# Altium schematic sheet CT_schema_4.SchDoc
size 309 x 315 mm
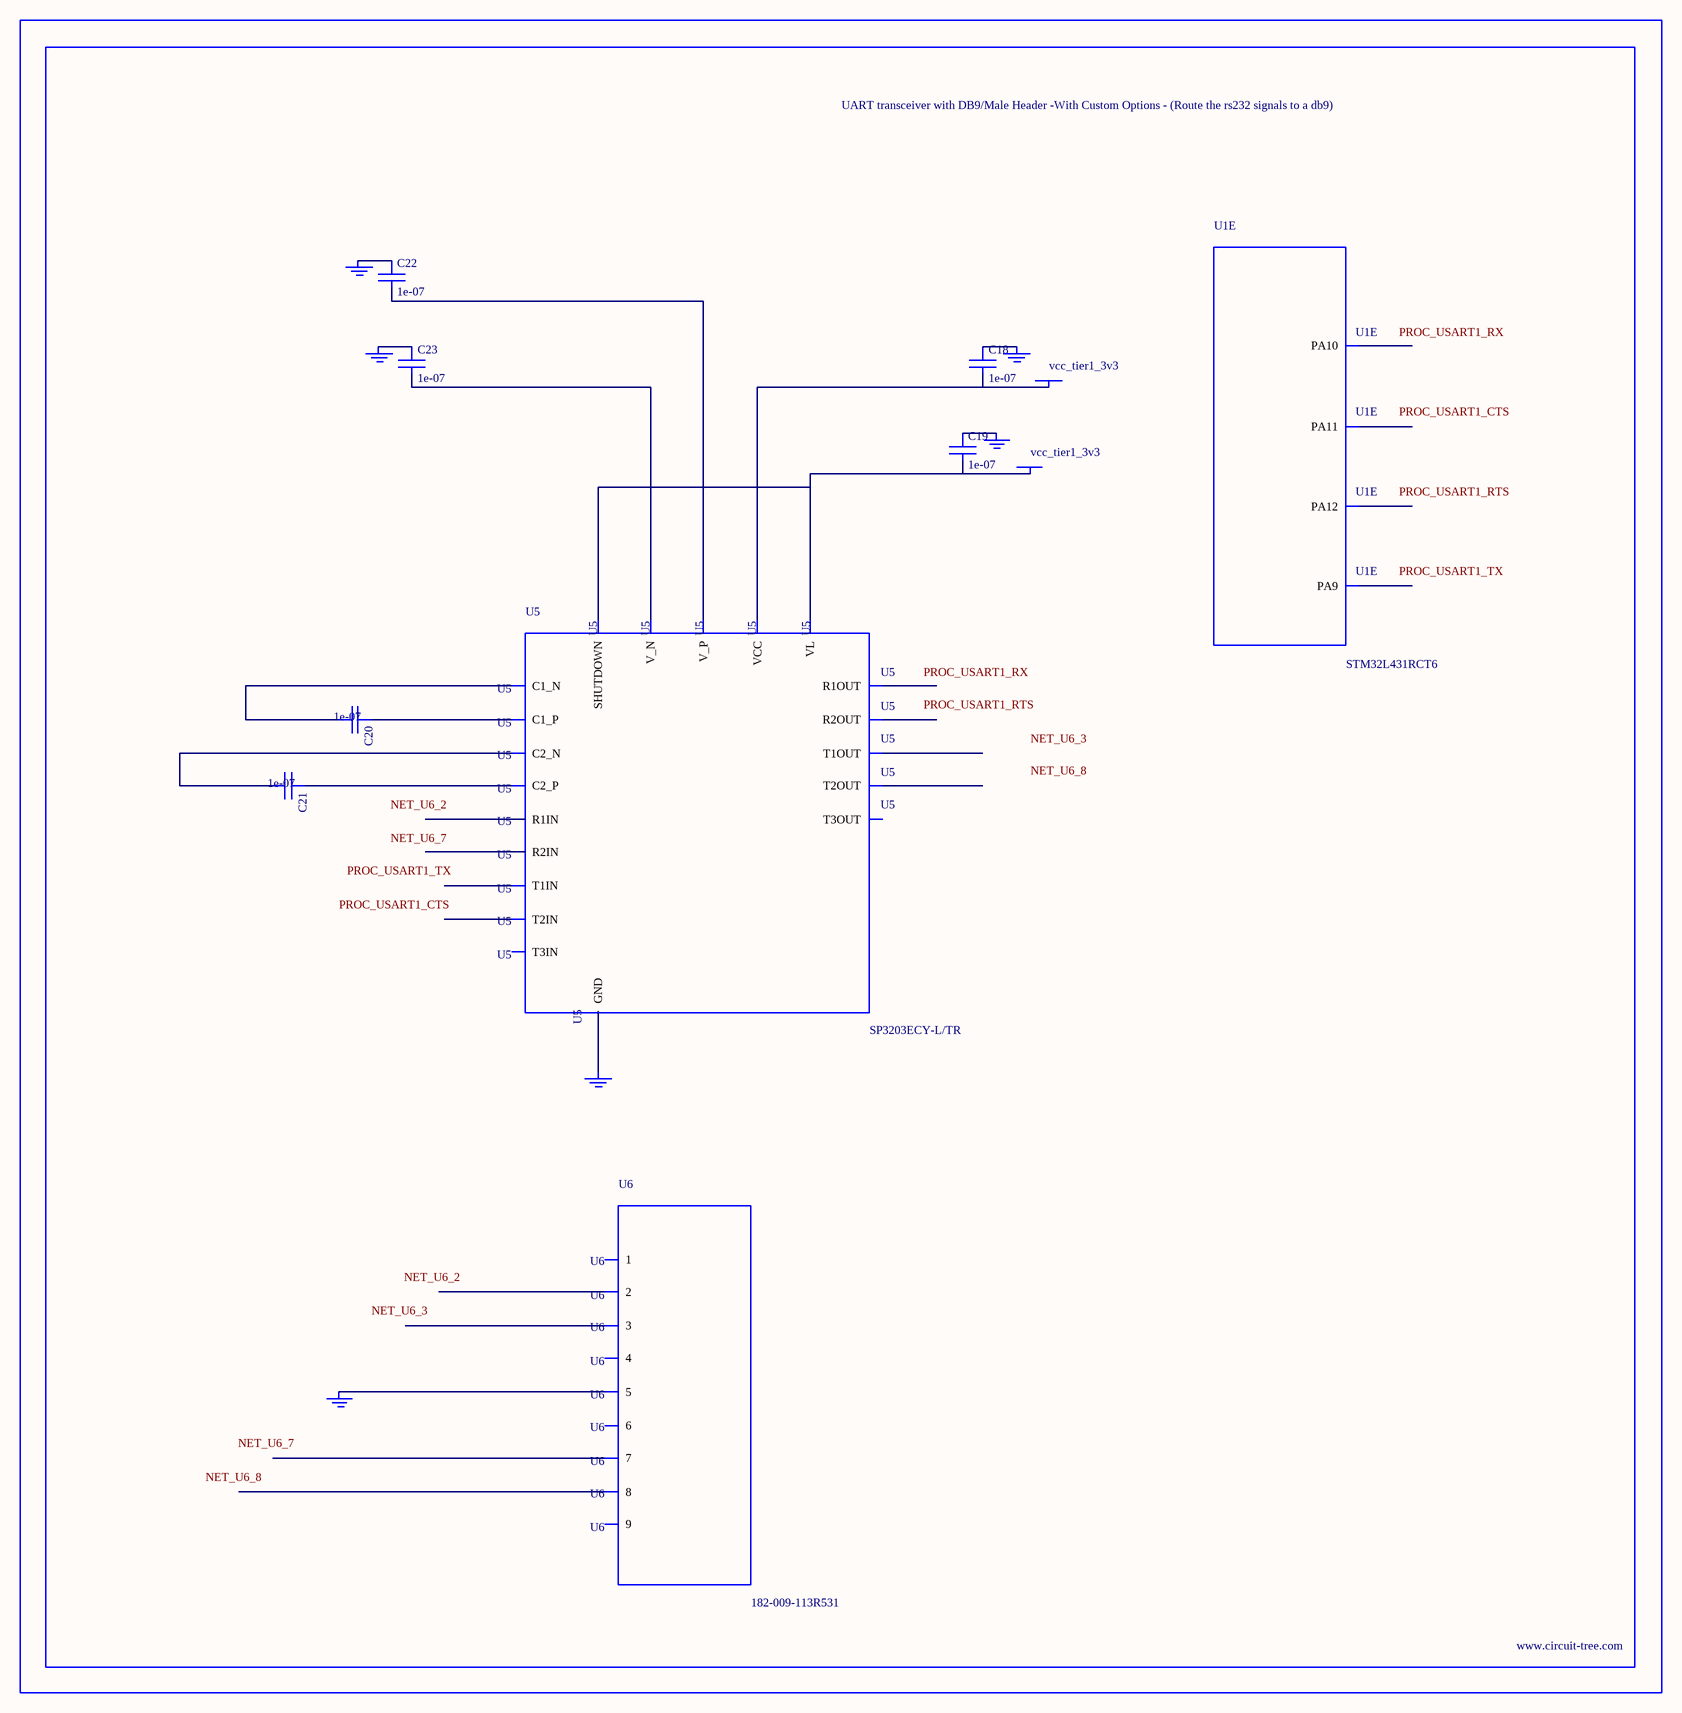
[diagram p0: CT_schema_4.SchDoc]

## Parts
BORDER3  (no value)
C18  1e-07  [C0402]
C19  1e-07  [C0402]
C20  1e-07  [C0402]
C21  1e-07  [C0402]
C22  1e-07  [C0402]
C23  1e-07  [C0402]
GND_INSTANCE_3_0  (no value)
GND_INSTANCE_3_1  (no value)
GND_INSTANCE_3_2  (no value)
GND_INSTANCE_3_3  (no value)
GND_INSTANCE_3_4  (no value)
GND_INSTANCE_3_5  (no value)
POWER_INSTANCE_3_0  vcc_tier1_3v3
POWER_INSTANCE_3_1  vcc_tier1_3v3
U1  STM32L431RCT6  [LQFP64]  (part E of 6)
U5  SP3203ECY-L/TR  [TSSOP20-I]
U6  182-009-113R531  [182-009-MALE]

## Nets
NetC18_1: C18.1 GND_INSTANCE_3_3.0(GND)
NetC18_2: C18.2 POWER_INSTANCE_3_1.0(PWR) U5.19(VCC)
NetC19_1: C19.1 GND_INSTANCE_3_2.0(GND)
NetC19_2: C19.2 POWER_INSTANCE_3_0.0(PWR) U5.12(VL) U5.20(SHUTDOWN)
NetC20_1: C20.1 U5.1(C1_P)
NetC20_2: C20.2 U5.3(C1_N)
NetC21_1: C21.1 U5.4(C2_P)
NetC21_2: C21.2 U5.5(C2_N)
NetC22_1: C22.1 GND_INSTANCE_3_0.0(GND)
NetC22_2: C22.2 U5.2(V_P)
NetC23_1: C23.1 GND_INSTANCE_3_1.0(GND)
NetC23_2: C23.2 U5.6(V_N)
NetGND_INSTANCE_3_4_0: GND_INSTANCE_3_4.0(GND) U5.18(GND)
NetGND_INSTANCE_3_5_0: GND_INSTANCE_3_5.0(GND) U6.5

Not connected (* = marked no-connect by the designer): U1 42(PA9) 43(PA10) 44(PA11) 45(PA12); U5 7(T1IN) 8(T2IN) 9(T3IN) 10(R2OUT) 11(R1OUT) 13(R2IN) 14(R1IN) 15(T3OUT) 16(T2OUT) 17(T1OUT); U6 1 2 3 4 6 7 8 9

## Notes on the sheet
- Labels drawn without touching a wire or pin: NET_U6_2, NET_U6_3, NET_U6_7, NET_U6_8, PROC_USART1_CTS, PROC_USART1_RTS, PROC_USART1_RX, PROC_USART1_TX

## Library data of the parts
BORDER3 = BORDER_PAGE3
C18-C23 = C0402C104K3RACTU
GND_INSTANCE_3_0-GND_INSTANCE_3_5 = GND
POWER_INSTANCE_3_0 POWER_INSTANCE_3_1 = PWR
